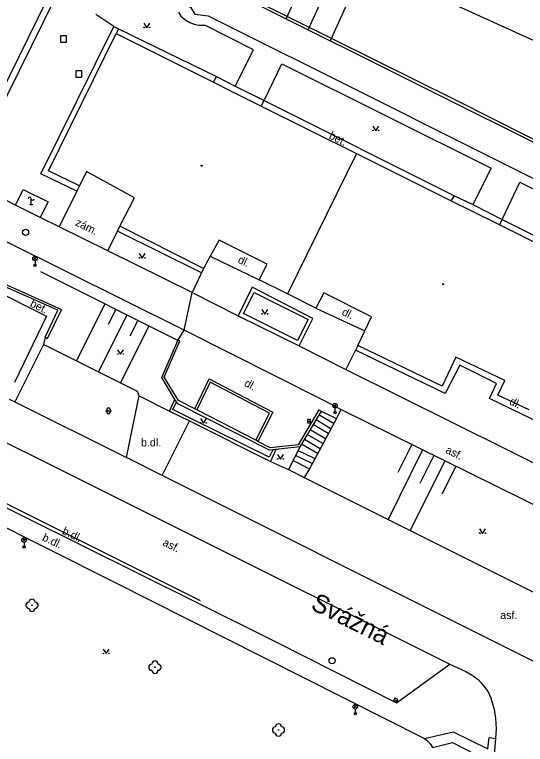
# Model space of a CAD drawing. Extents: x -602419 to -601554, y -1162937 to -1162362.
# Drawn here: x -602219.8 to -602178.2, y -1162567.9 to -1162508.7 of the extents above; entities that cross this region are included whole.
import ezdxf

# ---------------------------------------------------------------- set-up
doc = ezdxf.new("R2010")
doc.units = 0
doc.layers.add('Podklad', color=7, linetype='Continuous')

msp = doc.modelspace()

# ---------------------------------------------------------------- linework, layer by layer
at = {"layer": 'Podklad'}
for p, q in [((-602218.275, -1162524.1), (-602218.525, -1162524.1)), ((-602218.4, -1162524.1), (-602218.4, -1162523.6)), ((-602218.2225, -1162528.58), (-602217.9575, -1162528.315)), ((-602218.2225, -1162528.315), (-602217.9575, -1162528.58)), ((-602218.09, -1162528.635), (-602218.09, -1162529.01)), ((-602212.248, -1162540.703), (-602212.248, -1162540.953)), ((-602211.998, -1162540.703), (-602211.998, -1162540.953)), ((-602193.8524, -1162540.5399), (-602193.5874, -1162540.2749)), ((-602193.8524, -1162540.2749), (-602193.5874, -1162540.5399)), ((-602193.7199, -1162540.5949), (-602193.7199, -1162540.9699)), ((-602212.373, -1162540.828), (-602211.873, -1162540.828)), ((-602195.965, -1162541.67), (-602195.715, -1162541.67)), ((-602219.1125, -1162551.46), (-602218.8475, -1162551.195)), ((-602219.1125, -1162551.195), (-602218.8475, -1162551.46)), ((-602218.98, -1162551.515), (-602218.98, -1162551.89)), ((-602188.9015, -1162564.2835), (-602188.6785, -1162564.3965)), ((-602192.2025, -1162564.99), (-602191.9375, -1162564.725)), ((-602192.2025, -1162564.725), (-602191.9375, -1162564.99)), ((-602192.07, -1162565.045), (-602192.07, -1162565.42))]:
    msp.add_line(p, q, dxfattribs=at)
for points in [[(-602093.5, -1162548.86), (-602098.27, -1162558.35), (-602128.4, -1162543.44), (-602175.25, -1162520.19), (-602211.34, -1162502.17), (-602258.9099, -1162478.56)], [(-602183.86, -1162515.63), (-602230.46, -1162492.51)], [(-602209.38, -1162496.3), (-602093.68, -1162548.78)], [(-602194.92, -1162502.86), (-602197.7, -1162508.98)], [(-602193.1, -1162503.68), (-602195.9099, -1162509.87)], [(-602213.23, -1162504.25), (-602208.94, -1162506.34), (-602205.9699, -1162507.76), (-602205.46, -1162508.05), (-602205.1, -1162508.61), (-602204.02, -1162508.75), (-602190.62, -1162515.44), (-602184.43, -1162518.56)], [(-602191.28, -1162504.51), (-602194.12, -1162510.77)], [(-602225.3, -1162517.69), (-602222.31, -1162519.13), (-602216.4099, -1162507.18), (-602216.86, -1162506.95)], [(-602217.08, -1162507.31), (-602222.58, -1162518.48)], [(-602211.69, -1162509.61), (-602213.1599, -1162508.63)], [(-602206.44, -1162508.46), (-602206.24, -1162508.77), (-602205.95, -1162509.01), (-602205.85, -1162509.1), (-602205.52, -1162509.29), (-602205.17, -1162509.43), (-602204.79, -1162509.51), (-602204.29, -1162509.51)], [(-602214.68, -1162522.98), (-602217.63, -1162521.57), (-602211.69, -1162509.61), (-602211.3, -1162509.8)], [(-602211.3, -1162509.8), (-602211.5, -1162510.19)], [(-602211.3, -1162509.8), (-602203.35, -1162513.69)], [(-602209.25, -1162509.3449), (-602209, -1162509.7199), (-602208.75, -1162509.3449)], [(-602200.34, -1162511.52), (-602204.29, -1162509.51)], [(-602216.99, -1162521.33), (-602211.5, -1162510.19)], [(-602211.5, -1162510.19), (-602203.58, -1162514.15)], [(-602201.82, -1162514.46), (-602200.34, -1162511.52)], [(-602199.4699, -1162515.64), (-602198.04, -1162512.64)], [(-602198.04, -1162512.64), (-602181.02, -1162521.13)], [(-602203.58, -1162514.15), (-602203.35, -1162513.69)], [(-602203.35, -1162513.69), (-602201.82, -1162514.46)], [(-602203.58, -1162514.15), (-602202.04, -1162514.9099)], [(-602201.82, -1162514.46), (-602199.4699, -1162515.64)], [(-602202.04, -1162514.9099), (-602199.7199, -1162516.08)], [(-602199.7199, -1162516.08), (-602199.4699, -1162515.64)], [(-602199.4699, -1162515.64), (-602184.02, -1162523.37)], [(-602175.2199, -1162519.99), (-602183.86, -1162515.63)], [(-602199.7199, -1162516.08), (-602191.9699, -1162519.93)], [(-602190.65, -1162517.705), (-602190.4, -1162518.08), (-602190.15, -1162517.705)], [(-602184.43, -1162518.56), (-602175.96, -1162522.77), (-602175.53, -1162521.9)], [(-602191.9699, -1162519.93), (-602197.57, -1162531.34)], [(-602191.9699, -1162519.93), (-602184.27, -1162523.77)], [(-602219.67, -1162524.12), (-602226.67, -1162520.56)], [(-602181.02, -1162521.13), (-602182.52, -1162524.08)], [(-602214.48, -1162522.57), (-602216.99, -1162521.33)], [(-602213.9, -1162521.4), (-602214.48, -1162522.57)], [(-602210.02, -1162523.53), (-602213.9, -1162521.4)], [(-602180.13, -1162525.3), (-602178.69, -1162522.27)], [(-602178.69, -1162522.27), (-602161.28, -1162530.96)], [(-602219.67, -1162524.12), (-602219.05, -1162522.86), (-602217.03, -1162523.86), (-602217.6599, -1162525.12)], [(-602214.48, -1162522.57), (-602214.68, -1162522.98)], [(-602214.68, -1162522.98), (-602216.13, -1162525.88)], [(-602211.21, -1162525.84), (-602210.02, -1162523.53)], [(-602184.27, -1162523.77), (-602184.02, -1162523.37)], [(-602184.02, -1162523.37), (-602182.52, -1162524.08)], [(-602217.6599, -1162525.12), (-602219.67, -1162524.12)], [(-602184.27, -1162523.77), (-602182.75, -1162524.53)], [(-602182.52, -1162524.08), (-602180.13, -1162525.3)], [(-602205.98, -1162534.29), (-602225.28, -1162524.7), (-602225.44, -1162525.01)], [(-602182.75, -1162524.53), (-602180.33, -1162525.73)], [(-602216.13, -1162525.88), (-602217.6599, -1162525.12)], [(-602180.33, -1162525.73), (-602180.13, -1162525.3)], [(-602180.13, -1162525.3), (-602164.4099, -1162533.18)], [(-602212.17, -1162527.84), (-602216.13, -1162525.88)], [(-602211.4, -1162526.24), (-602211.21, -1162525.84)], [(-602204.39, -1162529.26), (-602211.21, -1162525.84)], [(-602180.33, -1162525.73), (-602172.46, -1162529.6599)], [(-602212.17, -1162527.84), (-602211.4, -1162526.24)], [(-602204.56, -1162529.62), (-602211.4, -1162526.24)], [(-602203.14, -1162526.98), (-602203.85, -1162528.28)], [(-602199.24, -1162528.93), (-602203.14, -1162526.98)], [(-602205.32, -1162531.23), (-602212.17, -1162527.84)], [(-602209.63, -1162528.065), (-602209.38, -1162528.44), (-602209.13, -1162528.065)], [(-602203.85, -1162528.28), (-602204.39, -1162529.26)], [(-602203.85, -1162528.28), (-602199.87, -1162530.18)], [(-602204.39, -1162529.26), (-602204.56, -1162529.62)], [(-602199.87, -1162530.18), (-602199.24, -1162528.93)], [(-602206.49, -1162535.12), (-602217.62, -1162529.53)], [(-602204.56, -1162529.62), (-602205.32, -1162531.23)], [(-602217.26, -1162534.86), (-602216.23, -1162532.6599), (-602221.52, -1162530.32)], [(-602221.43, -1162530.14), (-602215.94, -1162532.61)], [(-602197.57, -1162531.34), (-602199.87, -1162530.18)], [(-602221.76, -1162530.85), (-602217.1599, -1162533.13)], [(-602205.98, -1162534.29), (-602205.32, -1162531.23), (-602201.58, -1162533.11)], [(-602200.44, -1162530.78), (-602201.58, -1162533.11)], [(-602200.28, -1162531.2199), (-602195.9, -1162533.4099), (-602196.77, -1162535.13), (-602201.15, -1162532.92), (-602200.28, -1162531.2199)], [(-602195.52, -1162533.33), (-602200.44, -1162530.78)], [(-602194.64, -1162531.24), (-602195.27, -1162532.49)], [(-602190.75, -1162533.19), (-602194.64, -1162531.24)], [(-602195.27, -1162532.49), (-602197.57, -1162531.34)], [(-602212.42, -1162532.14), (-602214.73, -1162536.77)], [(-602215.94, -1162532.61), (-602217.1, -1162534.99), (-602217.26, -1162534.86)], [(-602210.63, -1162533.04), (-602212.93, -1162537.67)], [(-602211.53, -1162532.59), (-602212.14, -1162533.82)], [(-602199.67, -1162532.605), (-602199.42, -1162532.98), (-602199.17, -1162532.605)], [(-602195.27, -1162532.49), (-602191.3, -1162534.34)], [(-602217.1599, -1162533.13), (-602219.76, -1162538.52)], [(-602209.75, -1162533.49), (-602210.38, -1162534.76)], [(-602201.58, -1162533.11), (-602196.64, -1162535.54)], [(-602196.64, -1162535.54), (-602195.52, -1162533.33)], [(-602191.3, -1162534.34), (-602190.75, -1162533.19)], [(-602208.85, -1162533.94), (-602211.15, -1162538.56)], [(-602206.49, -1162535.12), (-602205.98, -1162534.29)], [(-602194.69, -1162539.96), (-602205.98, -1162534.29)], [(-602191.87, -1162535.53), (-602191.3, -1162534.34)], [(-602217.26, -1162534.86), (-602217.4, -1162535.44)], [(-602206.7199, -1162539.9), (-602207.79, -1162538.13), (-602206.49, -1162535.12)], [(-602207.59, -1162538.09), (-602206.33, -1162535.15)], [(-602206.33, -1162535.15), (-602206.49, -1162535.12)], [(-602217.4, -1162535.44), (-602219.74, -1162540.09)], [(-602209.64, -1162539.62), (-602209.77, -1162539.25), (-602217.4, -1162535.44)], [(-602211.39, -1162535.865), (-602211.14, -1162536.24), (-602210.89, -1162535.865)], [(-602196.64, -1162535.54), (-602192.83, -1162537.46)], [(-602192.06, -1162535.9099), (-602192.83, -1162537.46)], [(-602191.87, -1162535.53), (-602192.06, -1162535.9099)], [(-602165.52, -1162548.88), (-602172.67, -1162545.28), (-602171.56, -1162542.94), (-602174.62, -1162541.4699), (-602175.19, -1162542.7199), (-602181.18, -1162539.82), (-602180.59, -1162538.6), (-602183.59, -1162537.11), (-602184.76, -1162539.4099), (-602192.06, -1162535.9099)], [(-602185.01, -1162538.82), (-602191.87, -1162535.53)], [(-602183.89, -1162536.4699), (-602185.01, -1162538.82)], [(-602179.92, -1162538.37), (-602183.89, -1162536.4699)], [(-602192.83, -1162537.46), (-602166.4699, -1162550.58)], [(-602230.56, -1162538.37), (-602184.39, -1162561.4)], [(-602206.44, -1162539.99), (-602207.59, -1162538.09)], [(-602205.11, -1162540.67), (-602203.95, -1162538.23), (-602198.78, -1162540.93), (-602199.98, -1162543.31)], [(-602180.48, -1162539.55), (-602179.92, -1162538.37)], [(-602200.1599, -1162543.2199), (-602199.04, -1162541.01), (-602203.86, -1162538.5), (-602204.94, -1162540.76)], [(-602177.95, -1162540.76), (-602180.48, -1162539.55)], [(-602220.19, -1162539.87), (-602219.74, -1162540.09)], [(-602219.74, -1162540.09), (-602210.67, -1162544.62)], [(-602210.67, -1162544.62), (-602210.12, -1162541.98), (-602209.64, -1162539.62)], [(-602209.64, -1162539.62), (-602207.1599, -1162540.85)], [(-602207.1599, -1162540.85), (-602206.7199, -1162539.9)], [(-602198.76, -1162544), (-602199.06, -1162544.58), (-602205.39, -1162541.4699), (-602206.9, -1162540.71), (-602206.59, -1162540.11)], [(-602206.59, -1162540.11), (-602206.7199, -1162539.9)], [(-602198.76, -1162544), (-602199.03, -1162544.03), (-602206.5, -1162540.26), (-602206.59, -1162540.11)], [(-602205.11, -1162540.67), (-602206.44, -1162539.99)], [(-602193.25, -1162540.73), (-602194.69, -1162539.96)], [(-602204.94, -1162540.76), (-602205.11, -1162540.67)], [(-602193.25, -1162540.73), (-602193.61, -1162541.44)], [(-602167.89, -1162553.24), (-602193.25, -1162540.73)], [(-602207.1599, -1162540.85), (-602205.53, -1162541.64)], [(-602200.1599, -1162543.2199), (-602204.94, -1162540.76)], [(-602195.02, -1162540.75), (-602196.7, -1162543.58)], [(-602194.85, -1162540.85), (-602196.58, -1162543.76)], [(-602195.02, -1162540.75), (-602194.85, -1162540.85)], [(-602193.83, -1162541.85), (-602195.02, -1162541.15)], [(-602194.85, -1162540.85), (-602193.61, -1162541.44)], [(-602207.76, -1162546.07), (-602205.53, -1162541.64)], [(-602205.53, -1162541.64), (-602198.95, -1162544.94)], [(-602204.65, -1162541.455), (-602204.4, -1162541.83), (-602204.15, -1162541.455)], [(-602193.61, -1162541.44), (-602195.79, -1162545.53)], [(-602195.26, -1162541.54), (-602194.05, -1162542.26)], [(-602233.06, -1162542.2), (-602230.56, -1162543.6), (-602218.89, -1162549.46)], [(-602195.73, -1162542.34), (-602194.48, -1162543.08)], [(-602194.27, -1162542.67), (-602195.5, -1162541.94)], [(-602194.7, -1162543.49), (-602195.9699, -1162542.74)], [(-602230.31, -1162543.38), (-602218.64, -1162549.24), (-602204.67, -1162556.2199)], [(-602199.98, -1162543.31), (-602200.1599, -1162543.2199)], [(-602198.99, -1162543.83), (-602199.98, -1162543.31)], [(-602196.7, -1162543.58), (-602198.99, -1162543.83)], [(-602195.14, -1162544.3), (-602196.44, -1162543.53)], [(-602196.2, -1162543.14), (-602194.92, -1162543.9)], [(-602187.49, -1162543.57), (-602188.61, -1162545.83)], [(-602198.53, -1162543.98), (-602198.95, -1162544.94)], [(-602198.53, -1162543.98), (-602198.76, -1162544)], [(-602196.58, -1162543.76), (-602198.53, -1162543.98)], [(-602196.58, -1162543.76), (-602197.13, -1162544.87)], [(-602196.71, -1162544.04), (-602195.36, -1162544.71)], [(-602186.6, -1162544.01), (-602189.39, -1162549.6599)], [(-602207.76, -1162546.07), (-602210.67, -1162544.62)], [(-602198.39, -1162544.385), (-602198.14, -1162544.76), (-602197.89, -1162544.385)], [(-602197.13, -1162544.87), (-602197.49, -1162545.6)], [(-602197.13, -1162544.87), (-602195.79, -1162545.53)], [(-602195.57, -1162545.12), (-602196.92, -1162544.45)], [(-602185.7, -1162544.45), (-602186.82, -1162546.7199)], [(-602198.95, -1162544.94), (-602197.49, -1162545.6)], [(-602184.8, -1162544.9), (-602187.6, -1162550.56)], [(-602183.9099, -1162545.34), (-602185.03, -1162547.6)], [(-602157.2199, -1162571.37), (-602207.76, -1162546.07)], [(-602197.49, -1162545.6), (-602196.23, -1162546.24)], [(-602195.79, -1162545.53), (-602196.23, -1162546.24)], [(-602196.23, -1162546.24), (-602169.04, -1162559.84)], [(-602227.6, -1162546.74), (-602211.75, -1162554.7)], [(-602218.89, -1162549.46), (-602204.95, -1162556.4)], [(-602181.98, -1162550.415), (-602181.73, -1162550.79), (-602181.48, -1162550.415)], [(-602211.75, -1162554.7), (-602199.6599, -1162560.77)], [(-602204.95, -1162556.4), (-602198.68, -1162559.51)], [(-602198.68, -1162559.51), (-602188.71, -1162564.54)], [(-602212.56, -1162560.175), (-602212.31, -1162560.55), (-602212.06, -1162560.175)], [(-602199.6599, -1162560.77), (-602186.46, -1162567.45)], [(-602188.71, -1162564.54), (-602184.39, -1162561.4)], [(-602184.39, -1162561.4), (-602183.1, -1162562.01)], [(-602183.1, -1162562.01), (-602182.58, -1162562.31), (-602182.1, -1162562.6599), (-602181.88, -1162562.89), (-602181.51, -1162563.32), (-602181.25, -1162563.7), (-602181.05, -1162564.15), (-602180.78, -1162565.09), (-602180.68, -1162565.78), (-602180.62, -1162566.6599), (-602180.67, -1162567.45)], [(-602186.46, -1162567.45), (-602184.11, -1162566.9099), (-602181.31, -1162568.27), (-602181.2, -1162567.35), (-602180.67, -1162567.45)], [(-602186.46, -1162567.45), (-602186.21, -1162567.63), (-602185.96, -1162567.9), (-602185.8, -1162568.18)], [(-602185.8, -1162568.18), (-602184.17, -1162567.76), (-602181.38, -1162569.19), (-602181.48, -1162570.43), (-602180.93, -1162570.44)], [(-602180.67, -1162567.45), (-602180.93, -1162570.44)]]:
    msp.add_lwpolyline(points, dxfattribs=at)
for points in [[(-602216.03, -1162510.88), (-602215.53, -1162510.88), (-602215.53, -1162510.38), (-602216.03, -1162510.38)], [(-602214.78, -1162513.7199), (-602214.28, -1162513.7199), (-602214.28, -1162513.2199), (-602214.78, -1162513.2199)], [(-602195.965, -1162541.795), (-602195.715, -1162541.795), (-602195.715, -1162541.545), (-602195.965, -1162541.545)], [(-602188.958, -1162564.395), (-602188.735, -1162564.508), (-602188.622, -1162564.285), (-602188.845, -1162564.172)]]:
    msp.add_lwpolyline(points, close=True, dxfattribs=at)
for centre, radius in [((-602209.2251, -1162509.6948), 0.025), ((-602208.7754, -1162509.6948), 0.025), ((-602190.6251, -1162518.0549), 0.025), ((-602190.1754, -1162518.0549), 0.025), ((-602204.55, -1162520.92), 0.045), ((-602204.55, -1162520.92), 0.0199), ((-602218.86, -1162526.33), 0.25), ((-602218.09, -1162528.4475), 0.1875), ((-602209.6051, -1162528.4149), 0.025), ((-602209.1554, -1162528.4149), 0.025), ((-602218.09, -1162529.01), 0.1), ((-602218.09, -1162529.01), 0.0723), ((-602218.09, -1162529.01), 0.0438), ((-602184.94, -1162530.55), 0.045), ((-602184.94, -1162530.55), 0.0199), ((-602199.6451, -1162532.9549), 0.025), ((-602199.1954, -1162532.9549), 0.025), ((-602211.3651, -1162536.2149), 0.025), ((-602210.9154, -1162536.2149), 0.025), ((-602193.7199, -1162540.4074), 0.1875), ((-602193.7199, -1162540.9699), 0.1), ((-602193.7199, -1162540.9699), 0.0723), ((-602193.7199, -1162540.9699), 0.0438), ((-602204.6251, -1162541.8049), 0.025), ((-602204.1754, -1162541.8049), 0.025), ((-602198.3651, -1162544.7349), 0.025), ((-602197.9154, -1162544.7349), 0.025), ((-602181.9551, -1162550.7649), 0.025), ((-602181.5054, -1162550.7649), 0.025), ((-602218.98, -1162551.3275), 0.1875), ((-602218.98, -1162551.89), 0.1), ((-602218.98, -1162551.89), 0.0723), ((-602218.98, -1162551.89), 0.0438), ((-602218.34, -1162556.62), 0.025), ((-602212.5351, -1162560.5249), 0.025), ((-602212.0854, -1162560.5249), 0.025), ((-602193.95, -1162561.13), 0.25), ((-602208.35, -1162561.65), 0.025), ((-602192.07, -1162564.8575), 0.1875), ((-602192.07, -1162565.42), 0.1), ((-602192.07, -1162565.42), 0.0723), ((-602192.07, -1162565.42), 0.0438), ((-602198.31, -1162566.75), 0.025)]:
    msp.add_circle(centre, radius, dxfattribs=at)
for centre, radius, start, end in [((-602218.525, -1162523.6), 0.125, 0, 180), ((-602218.275, -1162523.6), 0.125, 180, 0), ((-602212.1229, -1162540.7031), 0.125, 0, 180), ((-602212.1229, -1162540.9531), 0.125, 180, 0), ((-602218.34, -1162556.37), 0.25, 0, 180), ((-602218.59, -1162556.62), 0.25, 90, 270), ((-602218.09, -1162556.62), 0.25, 270, 90), ((-602218.34, -1162556.87), 0.25, 180, 0), ((-602208.6, -1162561.65), 0.25, 90, 270), ((-602208.35, -1162561.4), 0.25, 0, 180), ((-602208.1, -1162561.65), 0.25, 270, 90), ((-602208.35, -1162561.9), 0.25, 180, 0), ((-602198.56, -1162566.75), 0.25, 90, 270), ((-602198.31, -1162566.5), 0.25, 0, 180), ((-602198.06, -1162566.75), 0.25, 270, 90), ((-602198.31, -1162567), 0.25, 180, 0)]:
    msp.add_arc(centre, radius, start, end, dxfattribs=at)

# ---------------------------------------------------------------- texts
for s, height, rotation, p in [('bet.', 0.65, 333.18, (-602194.26, -1162518.68)), (' zám.', 0.65, 333.74, (-602215.09, -1162525.63)), ('dl.', 0.65, 334.17, (-602201.67, -1162528.77)), ('bet.', 0.65, 333.82, (-602218.55, -1162532.32)), ('dl.', 0.65, 334.17, (-602193.2199, -1162533.01)), ('dl.', 0.65, 332.49, (-602201.15, -1162538.78)), ('dl.', 0.65, 334.17, (-602179.61, -1162540.27)), ('asf.', 0.65, 333.74, (-602184.8, -1162544.21)), ('b.dl.', 0.65, 334.59, (-602215.94, -1162550.81)), ('b.dl.', 0.65, 334.59, (-602217.56, -1162551.33)), ('asf.', 0.65, 333.97, (-602207.78, -1162551.73)), ('Svážná', 1.5, 333.6, (-602195.78, -1162556.9))]:
    msp.add_text(s, height=height, rotation=rotation, dxfattribs=at).set_placement(p)
for s, p in [('b.dl.', (-602209.48, -1162543.7199)), ('asf.', (-602180.3, -1162557.74))]:
    msp.add_text(s, height=0.65, dxfattribs=at).set_placement(p)

doc.saveas('drawing.dxf')
